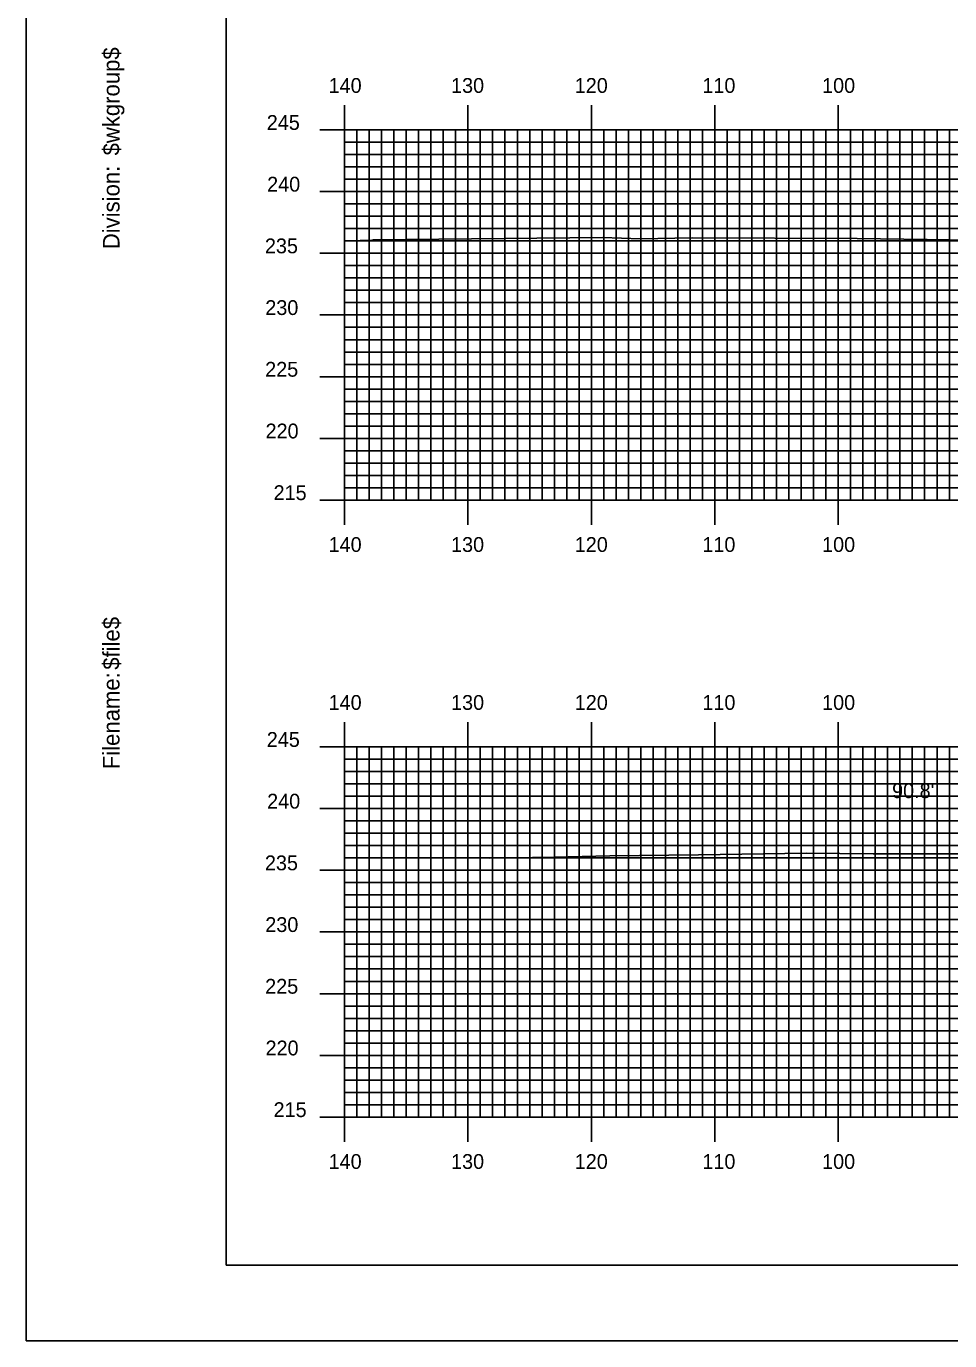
# Model space of a CAD drawing. Extents: x 1802716 to 1803060, y 442591 to 442811.
# Drawn here: x 1802716.3 to 1802791.1, y 442590.5 to 442697.1 of the extents above; entities that cross this region are included whole.
import ezdxf

# ---------------------------------------------------------------- set-up
doc = ezdxf.new("R2010")
doc.units = 0
for name, color, linetype in [('BORDER', 7, 'Continuous'), ('D_Text_Standard', 7, 'Continuous'), ('H_V ANNOTATION', 7, 'Continuous'), ('MAJOR', 7, 'Continuous'), ('MINOR', 7, 'Continuous'), ('PLOT BOUNDARY', 7, 'Continuous'), ('S_Roadway_Centerline', 7, 'Continuous')]:
    doc.layers.add(name, color=color, linetype=linetype)

msp = doc.modelspace()

# ---------------------------------------------------------------- linework, layer by layer
at = {"layer": 'BORDER'}
msp.add_lwpolyline([(1802732.51, 442596.67), (1803052.51, 442596.67), (1803052.51, 442806.67), (1802732.51, 442806.67)], close=True, dxfattribs=at)
at = {"layer": 'MAJOR'}
for p, q in [((1802742.11, 442690.67), (1802742.11, 442688.67)), ((1802752.11, 442690.67), (1802752.11, 442688.67)), ((1802762.11, 442690.67), (1802762.11, 442688.67)), ((1802772.11, 442690.67), (1802772.11, 442688.67)), ((1802782.11, 442690.67), (1802782.11, 442688.67)), ((1802740.11, 442688.67), (1802742.11, 442688.67)), ((1802742.11, 442688.67), (1803022.11, 442688.67)), ((1802742.11, 442658.67), (1802742.11, 442688.67)), ((1802742.11, 442658.67), (1802742.11, 442688.67)), ((1802742.11, 442688.67), (1803022.11, 442688.67)), ((1802752.11, 442658.67), (1802752.11, 442688.67)), ((1802762.11, 442658.67), (1802762.11, 442688.67)), ((1802772.11, 442658.67), (1802772.11, 442688.67)), ((1802782.11, 442658.67), (1802782.11, 442688.67)), ((1802740.11, 442683.67), (1802742.11, 442683.67)), ((1802742.11, 442683.67), (1803022.11, 442683.67)), ((1802740.11, 442678.67), (1802742.11, 442678.67)), ((1802742.11, 442678.67), (1803022.11, 442678.67)), ((1802740.11, 442673.67), (1802742.11, 442673.67)), ((1802742.11, 442673.67), (1803022.11, 442673.67)), ((1802740.11, 442668.67), (1802742.11, 442668.67)), ((1802742.11, 442668.67), (1803022.11, 442668.67)), ((1802740.11, 442663.67), (1802742.11, 442663.67)), ((1802742.11, 442663.67), (1803022.11, 442663.67)), ((1802740.11, 442658.67), (1802742.11, 442658.67)), ((1802742.11, 442658.67), (1803022.11, 442658.67)), ((1802742.11, 442658.67), (1803022.11, 442658.67)), ((1802742.11, 442656.66), (1802742.11, 442658.67)), ((1802752.11, 442656.66), (1802752.11, 442658.67)), ((1802762.11, 442656.66), (1802762.11, 442658.67)), ((1802772.11, 442656.66), (1802772.11, 442658.67)), ((1802782.11, 442656.66), (1802782.11, 442658.67)), ((1802742.11, 442640.67), (1802742.11, 442638.67)), ((1802752.11, 442640.67), (1802752.11, 442638.67)), ((1802762.11, 442640.67), (1802762.11, 442638.67)), ((1802772.11, 442640.67), (1802772.11, 442638.67)), ((1802782.11, 442640.67), (1802782.11, 442638.67)), ((1802740.11, 442638.67), (1802742.11, 442638.67)), ((1802742.11, 442638.67), (1803022.11, 442638.67)), ((1802742.11, 442608.67), (1802742.11, 442638.67)), ((1802742.11, 442608.67), (1802742.11, 442638.67)), ((1802742.11, 442638.67), (1803022.11, 442638.67)), ((1802752.11, 442608.67), (1802752.11, 442638.67)), ((1802762.11, 442608.67), (1802762.11, 442638.67)), ((1802772.11, 442608.67), (1802772.11, 442638.67)), ((1802782.11, 442608.67), (1802782.11, 442638.67)), ((1802740.11, 442633.67), (1802742.11, 442633.67)), ((1802742.11, 442633.67), (1803022.11, 442633.67)), ((1802740.11, 442628.67), (1802742.11, 442628.67)), ((1802742.11, 442628.67), (1803022.11, 442628.67)), ((1802740.11, 442623.67), (1802742.11, 442623.67)), ((1802742.11, 442623.67), (1803022.11, 442623.67)), ((1802740.11, 442618.67), (1802742.11, 442618.67)), ((1802742.11, 442618.67), (1803022.11, 442618.67)), ((1802740.11, 442613.67), (1802742.11, 442613.67)), ((1802742.11, 442613.67), (1803022.11, 442613.67)), ((1802740.11, 442608.67), (1802742.11, 442608.67)), ((1802742.11, 442608.67), (1803022.11, 442608.67)), ((1802742.11, 442608.67), (1803022.11, 442608.67)), ((1802742.11, 442606.66), (1802742.11, 442608.67)), ((1802752.11, 442606.66), (1802752.11, 442608.67)), ((1802762.11, 442606.66), (1802762.11, 442608.67)), ((1802772.11, 442606.66), (1802772.11, 442608.67)), ((1802782.11, 442606.66), (1802782.11, 442608.67))]:
    msp.add_line(p, q, dxfattribs=at)
at = {"layer": 'MINOR'}
for p, q in [((1802743.11, 442658.67), (1802743.11, 442688.67)), ((1802744.11, 442658.67), (1802744.11, 442688.67)), ((1802745.11, 442658.67), (1802745.11, 442688.67)), ((1802746.11, 442658.67), (1802746.11, 442688.67)), ((1802747.11, 442658.67), (1802747.11, 442688.67)), ((1802748.11, 442658.67), (1802748.11, 442688.67)), ((1802749.11, 442658.67), (1802749.11, 442688.67)), ((1802750.11, 442658.67), (1802750.11, 442688.67)), ((1802751.11, 442658.67), (1802751.11, 442688.67)), ((1802753.11, 442658.67), (1802753.11, 442688.67)), ((1802754.11, 442658.67), (1802754.11, 442688.67)), ((1802755.11, 442658.67), (1802755.11, 442688.67)), ((1802756.11, 442658.67), (1802756.11, 442688.67)), ((1802757.11, 442658.67), (1802757.11, 442688.67)), ((1802758.11, 442658.67), (1802758.11, 442688.67)), ((1802759.11, 442658.67), (1802759.11, 442688.67)), ((1802760.11, 442658.67), (1802760.11, 442688.67)), ((1802761.11, 442658.67), (1802761.11, 442688.67)), ((1802763.11, 442658.67), (1802763.11, 442688.67)), ((1802764.11, 442658.67), (1802764.11, 442688.67)), ((1802765.11, 442658.67), (1802765.11, 442688.67)), ((1802766.11, 442658.67), (1802766.11, 442688.67)), ((1802767.11, 442658.67), (1802767.11, 442688.67)), ((1802768.11, 442658.67), (1802768.11, 442688.67)), ((1802769.11, 442658.67), (1802769.11, 442688.67)), ((1802770.11, 442658.67), (1802770.11, 442688.67)), ((1802771.11, 442658.67), (1802771.11, 442688.67)), ((1802773.11, 442658.67), (1802773.11, 442688.67)), ((1802774.11, 442658.67), (1802774.11, 442688.67)), ((1802775.11, 442658.67), (1802775.11, 442688.67)), ((1802776.11, 442658.67), (1802776.11, 442688.67)), ((1802777.11, 442658.67), (1802777.11, 442688.67)), ((1802778.11, 442658.67), (1802778.11, 442688.67)), ((1802779.11, 442658.67), (1802779.11, 442688.67)), ((1802780.11, 442658.67), (1802780.11, 442688.67)), ((1802781.11, 442658.67), (1802781.11, 442688.67)), ((1802783.11, 442658.67), (1802783.11, 442688.67)), ((1802784.11, 442658.67), (1802784.11, 442688.67)), ((1802785.11, 442658.67), (1802785.11, 442688.67)), ((1802786.11, 442658.67), (1802786.11, 442688.67)), ((1802787.11, 442658.67), (1802787.11, 442688.67)), ((1802788.11, 442658.67), (1802788.11, 442688.67)), ((1802789.11, 442658.67), (1802789.11, 442688.67)), ((1802790.11, 442658.67), (1802790.11, 442688.67)), ((1802791.11, 442658.67), (1802791.11, 442688.67)), ((1802742.11, 442687.67), (1803022.11, 442687.67)), ((1802742.11, 442687.67), (1802744.12, 442687.67)), ((1802742.11, 442686.67), (1803022.11, 442686.67)), ((1802742.11, 442686.67), (1802744.12, 442686.67)), ((1802742.11, 442685.67), (1803022.11, 442685.67)), ((1802742.11, 442685.67), (1802744.12, 442685.67)), ((1802742.11, 442684.67), (1803022.11, 442684.67)), ((1802742.11, 442684.67), (1802744.12, 442684.67)), ((1802742.11, 442682.67), (1803022.11, 442682.67)), ((1802742.11, 442682.67), (1802744.12, 442682.67)), ((1802742.11, 442681.67), (1803022.11, 442681.67)), ((1802742.11, 442681.67), (1802744.12, 442681.67)), ((1802742.11, 442680.67), (1803022.11, 442680.67)), ((1802742.11, 442680.67), (1802744.12, 442680.67)), ((1802742.11, 442679.67), (1803022.11, 442679.67)), ((1802742.11, 442679.67), (1802744.12, 442679.67)), ((1802742.11, 442677.67), (1803022.11, 442677.67)), ((1802742.11, 442677.67), (1802744.12, 442677.67)), ((1802742.11, 442676.67), (1803022.11, 442676.67)), ((1802742.11, 442676.67), (1802744.12, 442676.67)), ((1802742.11, 442675.67), (1803022.11, 442675.67)), ((1802742.11, 442675.67), (1802744.12, 442675.67)), ((1802742.11, 442674.67), (1803022.11, 442674.67)), ((1802742.11, 442674.67), (1802744.12, 442674.67)), ((1802742.11, 442672.67), (1803022.11, 442672.67)), ((1802742.11, 442672.67), (1802744.12, 442672.67)), ((1802742.11, 442671.67), (1803022.11, 442671.67)), ((1802742.11, 442671.67), (1802744.12, 442671.67)), ((1802742.11, 442670.67), (1803022.11, 442670.67)), ((1802742.11, 442670.67), (1802744.12, 442670.67)), ((1802742.11, 442669.67), (1803022.11, 442669.67)), ((1802742.11, 442669.67), (1802744.12, 442669.67)), ((1802742.11, 442667.67), (1803022.11, 442667.67)), ((1802742.11, 442667.67), (1802744.12, 442667.67)), ((1802742.11, 442666.67), (1803022.11, 442666.67)), ((1802742.11, 442666.67), (1802744.12, 442666.67)), ((1802742.11, 442665.67), (1803022.11, 442665.67)), ((1802742.11, 442665.67), (1802744.12, 442665.67)), ((1802742.11, 442664.67), (1803022.11, 442664.67)), ((1802742.11, 442664.67), (1802744.12, 442664.67)), ((1802742.11, 442662.67), (1803022.11, 442662.67)), ((1802742.11, 442662.67), (1802744.12, 442662.67)), ((1802742.11, 442661.67), (1803022.11, 442661.67)), ((1802742.11, 442661.67), (1802744.12, 442661.67)), ((1802742.11, 442660.67), (1803022.11, 442660.67)), ((1802742.11, 442660.67), (1802744.12, 442660.67)), ((1802742.11, 442659.67), (1803022.11, 442659.67)), ((1802742.11, 442659.67), (1802744.12, 442659.67)), ((1802742.11, 442637.67), (1803022.11, 442637.67)), ((1802742.11, 442637.67), (1802744.12, 442637.67)), ((1802743.11, 442608.67), (1802743.11, 442638.67)), ((1802744.11, 442608.67), (1802744.11, 442638.67)), ((1802745.11, 442608.67), (1802745.11, 442638.67)), ((1802746.11, 442608.67), (1802746.11, 442638.67)), ((1802747.11, 442608.67), (1802747.11, 442638.67)), ((1802748.11, 442608.67), (1802748.11, 442638.67)), ((1802749.11, 442608.67), (1802749.11, 442638.67)), ((1802750.11, 442608.67), (1802750.11, 442638.67)), ((1802751.11, 442608.67), (1802751.11, 442638.67)), ((1802753.11, 442608.67), (1802753.11, 442638.67)), ((1802754.11, 442608.67), (1802754.11, 442638.67)), ((1802755.11, 442608.67), (1802755.11, 442638.67)), ((1802756.11, 442608.67), (1802756.11, 442638.67)), ((1802757.11, 442608.67), (1802757.11, 442638.67)), ((1802758.11, 442608.67), (1802758.11, 442638.67)), ((1802759.11, 442608.67), (1802759.11, 442638.67)), ((1802760.11, 442608.67), (1802760.11, 442638.67)), ((1802761.11, 442608.67), (1802761.11, 442638.67)), ((1802763.11, 442608.67), (1802763.11, 442638.67)), ((1802764.11, 442608.67), (1802764.11, 442638.67)), ((1802765.11, 442608.67), (1802765.11, 442638.67)), ((1802766.11, 442608.67), (1802766.11, 442638.67)), ((1802767.11, 442608.67), (1802767.11, 442638.67)), ((1802768.11, 442608.67), (1802768.11, 442638.67)), ((1802769.11, 442608.67), (1802769.11, 442638.67)), ((1802770.11, 442608.67), (1802770.11, 442638.67)), ((1802771.11, 442608.67), (1802771.11, 442638.67)), ((1802773.11, 442608.67), (1802773.11, 442638.67)), ((1802774.11, 442608.67), (1802774.11, 442638.67)), ((1802775.11, 442608.67), (1802775.11, 442638.67)), ((1802776.11, 442608.67), (1802776.11, 442638.67)), ((1802777.11, 442608.67), (1802777.11, 442638.67)), ((1802778.11, 442608.67), (1802778.11, 442638.67)), ((1802779.11, 442608.67), (1802779.11, 442638.67)), ((1802780.11, 442608.67), (1802780.11, 442638.67)), ((1802781.11, 442608.67), (1802781.11, 442638.67)), ((1802783.11, 442608.67), (1802783.11, 442638.67)), ((1802784.11, 442608.67), (1802784.11, 442638.67)), ((1802785.11, 442608.67), (1802785.11, 442638.67)), ((1802786.11, 442608.67), (1802786.11, 442638.67)), ((1802787.11, 442608.67), (1802787.11, 442638.67)), ((1802788.11, 442608.67), (1802788.11, 442638.67)), ((1802789.11, 442608.67), (1802789.11, 442638.67)), ((1802790.11, 442608.67), (1802790.11, 442638.67)), ((1802791.11, 442608.67), (1802791.11, 442638.67)), ((1802742.11, 442636.67), (1803022.11, 442636.67)), ((1802742.11, 442636.67), (1802744.12, 442636.67)), ((1802742.11, 442635.67), (1803022.11, 442635.67)), ((1802742.11, 442635.67), (1802744.12, 442635.67)), ((1802742.11, 442634.67), (1803022.11, 442634.67)), ((1802742.11, 442634.67), (1802744.12, 442634.67)), ((1802742.11, 442632.67), (1803022.11, 442632.67)), ((1802742.11, 442632.67), (1802744.12, 442632.67)), ((1802742.11, 442631.67), (1803022.11, 442631.67)), ((1802742.11, 442631.67), (1802744.12, 442631.67)), ((1802742.11, 442630.67), (1803022.11, 442630.67)), ((1802742.11, 442630.67), (1802744.12, 442630.67)), ((1802742.11, 442629.67), (1803022.11, 442629.67)), ((1802742.11, 442629.67), (1802744.12, 442629.67)), ((1802742.11, 442627.67), (1803022.11, 442627.67)), ((1802742.11, 442627.67), (1802744.12, 442627.67)), ((1802742.11, 442626.67), (1803022.11, 442626.67)), ((1802742.11, 442626.67), (1802744.12, 442626.67)), ((1802742.11, 442625.67), (1803022.11, 442625.67)), ((1802742.11, 442625.67), (1802744.12, 442625.67)), ((1802742.11, 442624.67), (1803022.11, 442624.67)), ((1802742.11, 442624.67), (1802744.12, 442624.67)), ((1802742.11, 442622.67), (1803022.11, 442622.67)), ((1802742.11, 442622.67), (1802744.12, 442622.67)), ((1802742.11, 442621.67), (1803022.11, 442621.67)), ((1802742.11, 442621.67), (1802744.12, 442621.67)), ((1802742.11, 442620.67), (1803022.11, 442620.67)), ((1802742.11, 442620.67), (1802744.12, 442620.67)), ((1802742.11, 442619.67), (1803022.11, 442619.67)), ((1802742.11, 442619.67), (1802744.12, 442619.67)), ((1802742.11, 442617.67), (1803022.11, 442617.67)), ((1802742.11, 442617.67), (1802744.12, 442617.67)), ((1802742.11, 442616.67), (1803022.11, 442616.67)), ((1802742.11, 442616.67), (1802744.12, 442616.67)), ((1802742.11, 442615.67), (1803022.11, 442615.67)), ((1802742.11, 442615.67), (1802744.12, 442615.67)), ((1802742.11, 442614.67), (1803022.11, 442614.67)), ((1802742.11, 442614.67), (1802744.12, 442614.67)), ((1802742.11, 442612.67), (1803022.11, 442612.67)), ((1802742.11, 442612.67), (1802744.12, 442612.67)), ((1802742.11, 442611.67), (1803022.11, 442611.67)), ((1802742.11, 442611.67), (1802744.12, 442611.67)), ((1802742.11, 442610.67), (1803022.11, 442610.67)), ((1802742.11, 442610.67), (1802744.12, 442610.67)), ((1802742.11, 442609.67), (1803022.11, 442609.67)), ((1802742.11, 442609.67), (1802744.12, 442609.67))]:
    msp.add_line(p, q, dxfattribs=at)
at = {"layer": 'PLOT BOUNDARY'}
msp.add_lwpolyline([(1802716.33, 442590.55), (1803056.33, 442590.55), (1803056.33, 442810.55), (1802716.33, 442810.55)], close=True, dxfattribs=at)
at = {"layer": 'S_Roadway_Centerline'}
for points in [[(1802742.11, 442679.69), (1802742.42, 442679.69), (1802744.31, 442679.73), (1802744.42, 442679.76), (1802763, 442679.96), (1802766.1, 442679.85), (1802770.27, 442679.92), (1802783.65, 442679.88), (1802796.84, 442679.67)], [(1802742.11, 442629.69), (1802742.78, 442629.69), (1802753.85, 442629.65), (1802759.09, 442629.74), (1802763.61, 442629.83), (1802770.8, 442629.92), (1802779.53, 442630.06), (1802784.94, 442630.01), (1802794.27, 442630)]]:
    msp.add_lwpolyline(points, dxfattribs=at)

# ---------------------------------------------------------------- texts
at = {"layer": 'BORDER'}
for s, p in [('$wkgroup$', (1802723.88, 442686.6)), ('Division:', (1802723.88, 442679)), ('$file$', (1802723.88, 442644.92)), ('Filename:', (1802723.88, 442636.86))]:
    msp.add_text(s, height=1.339, rotation=90, dxfattribs=at).set_placement(p)
at = {"layer": 'D_Text_Standard'}
msp.add_text("90.8'", height=1.2, dxfattribs=at).set_placement((1802786.47, 442634.52))
at = {"layer": 'H_V ANNOTATION'}
for s, p in [('140', (1802740.82, 442691.67)), ('130', (1802750.74, 442691.67)), ('120', (1802760.76, 442691.67)), ('110', (1802771.1, 442691.67)), ('100', (1802780.8, 442691.67)), ('245', (1802735.81, 442688.67)), ('240', (1802735.84, 442683.67)), ('235', (1802735.66, 442678.67)), ('230', (1802735.69, 442673.67)), ('225', (1802735.68, 442668.67)), ('220', (1802735.71, 442663.67)), ('215', (1802736.36, 442658.67)), ('140', (1802740.82, 442654.47)), ('130', (1802750.74, 442654.47)), ('120', (1802760.76, 442654.47)), ('110', (1802771.1, 442654.47)), ('100', (1802780.8, 442654.47)), ('140', (1802740.82, 442641.67)), ('130', (1802750.74, 442641.67)), ('120', (1802760.76, 442641.67)), ('110', (1802771.1, 442641.67)), ('100', (1802780.8, 442641.67)), ('245', (1802735.81, 442638.67)), ('240', (1802735.84, 442633.67)), ('235', (1802735.66, 442628.67)), ('230', (1802735.69, 442623.67)), ('225', (1802735.68, 442618.67)), ('220', (1802735.71, 442613.67)), ('215', (1802736.36, 442608.67)), ('140', (1802740.82, 442604.47)), ('130', (1802750.74, 442604.47)), ('120', (1802760.76, 442604.47)), ('110', (1802771.1, 442604.47)), ('100', (1802780.8, 442604.47))]:
    msp.add_text(s, height=1.2, dxfattribs=at).set_placement(p)
at = {"layer": 'MAJOR'}
for p in [(1802742.11, 442658.67), (1802742.11, 442608.67)]:
    msp.add_text('-', height=0.012, dxfattribs=at).set_placement(p)

doc.saveas('drawing.dxf')
